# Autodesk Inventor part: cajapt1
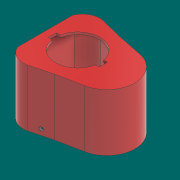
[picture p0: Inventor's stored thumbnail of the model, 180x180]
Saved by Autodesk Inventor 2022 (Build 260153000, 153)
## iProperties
Created: 2021-11
Part Number: cajapt1
Material: Generic
Document SubType Name: Modeling
Designer: santi
Density: 1 g/cm^3
Appearance: Default
Author: santi
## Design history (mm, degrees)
sketch "Sketch1"
  geometry: C1 r 21 at (0, 0); C2 r 20 at (0, 0); 1 further point
  constraints: 2 centre point, 1 coincident
  dimensions: "d0" = 42 diameter of C1; "d1" = 1 radial gap between concentric circles of C1 C2
extrude "Extrusion1" new body sketch "Sketch1" distance "d2" = 15; taper "d3" = 0 deg
sketch "Sketch2" dims "d4" = 48
  geometry: L1 (-24, 0)-(-24, 5.5); L2 (-24, 5.5)-(-24, -5.5); L3 (-24, -5.5)-(-20.267, -5.5); L4 (-24, 5.5)-(-20.267, 5.5); L5 (0, 0)-(0, 10.729); L6 (24, 0)-(24, 5.5); L7 (24, 5.5)-(24, -5.5); L8 (24, -5.5)-(20.267, -5.5); L9 (24, 5.5)-(20.267, 5.5); L10 (23, 5.5)-(23, -4.5); L11 (23, -4.5)-(20.267, -4.5); L12 (24, 4.5)-(20.267, 4.5); L13 (-23, 5.5)-(-23, -4.5); L14 (-23, -4.5)-(-20.267, -4.5); L15 (-24, 4.5)-(-20.267, 4.5); C1 r 21 at (0, 0) reference; C2 r 23 at (0, 0); C3 r 21 at (0, 0); C4 r 23 at (0, 0); A1 r 21 centre (0, 0) between (-20.267, -5.5) and (-20.267, 5.5) reference; A2 r 21 centre (0, 0) between (20.267, -5.5) and (20.267, 5.5); 16 further points
  constraints: 30 end point, 5 symmetric about line, 4 centre point, 4 point on circle, 4 vertical, 2 coincident, 2 parallel, 2 perpendicular, 2 point on line, 1 horizontal alignment, 10 other
  dimensions: "d5" = 1 dimension on C2; "d6" = 5.5 distance of L1.start L1.end; "d7" = 11 distance of L1.end L2.end; "d8" = 1 distance between parallel lines of L7 L10; "d9" = 1 distance between parallel lines of L9 L12; "d10" = 1 distance between parallel lines of L2 L13; "d11" = 1 distance between parallel lines of L4 L15
extrude "Extrusion2" join sketch "Sketch2" distance "d12" = 15; taper "d13" = 0 deg
sketch "Sketch3"
  geometry: L1 (-20.512, 4.5)-(20.512, 4.5); L2 (-20.512, -4.5)-(20.512, -4.5); A1 r 21 centre (0, 0) between (-20.512, 4.5) and (-20.512, -4.5) reference; A2 r 21 centre (0, 0) between (20.512, -4.5) and (20.512, 4.5) reference; A3 r 21 centre (0, 0) between (20.512, -4.5) and (20.512, 4.5) reference; 1 further point
  constraints: 4 end point, 2 horizontal
extrude "Extrusion3" cut sketch "Sketch3" distance "d14" = 15; taper "d15" = 0 deg
workplane "Work Plane1"
sketch "Sketch4"
  geometry: C1 r 15 at (0, 0); 1 further point
  constraints: 1 centre point, 1 coincident
  dimensions: "d17" = 30 diameter of C1
sketch "Sketch5"
  geometry: L1 (-24, -5.5)-(-20.267, -5.5) reference; L2 (-24, 5.5)-(-24, -5.5) reference; L3 (-20.267, 5.5)-(-24, 5.5) reference; L4 (23.361, 5.5)-(20.267, 5.5) reference; L5 (20.267, -5.5)-(23.361, -5.5) reference; A1 r 21 centre (0, 0) between (-20.267, -5.5) and (20.267, -5.5) reference; A2 r 21 centre (0, 0) between (20.267, 5.5) and (-20.267, 5.5) reference; A3 r 24 centre (0, 0) between (23.361, -5.5) and (23.361, 5.5) reference; 1 further point
loft "Loft1" dims "d18" = 0, "d19" = 90 deg, "d20" = 0, "d21" = 90 deg
  node "Edges1"
sketch "Sketch6"
  geometry: C1 r 6.5 at (0, 0); C2 r 5.5 at (0, 0); 1 further point
  constraints: 2 centre point, 1 coincident
  dimensions: "d22" = 13 diameter of C1; "d23" = 1 radial gap between concentric circles of C1 C2
extrude "Extrusion4" join sketch "Sketch6" distance "d24" = 2; taper "d25" = 0 deg
sketch "Sketch7"
  geometry: C1 r 5.5 at (0, 0) reference; 1 further point
extrude "Extrusion5" cut sketch "Sketch7" distance "d26" = 6; taper "d27" = 0 deg
sketch "Sketch8"
  geometry: L1 (-20.19, 4.5)-(-20.19, -5.5); L2 (-20.19, -5.5)-(-20.19, 14.5); C1 r 2.5 at (-20.19, 14.5); C2 r 2.5 at (-20.19, -5.5)
  constraints: 4 end point, 2 centre point, 2 coincident, 1 point on line, 1 vertical
  dimensions: "d28" = 10 distance of L1.start L1.end; "d29" = 20 distance of L1.end L2.end; "d30" = 5 diameter of C1; "d31" = 5 diameter of C2
extrude "Extrusion6" cut sketch "Sketch8" distance "d32" = 10; taper "d33" = 0 deg
workplane "Work Plane2"
sketch "Sketch9"
  geometry: L1 (-20.206, 4.5)-(-22.555, 4.5) reference; L2 (-22.555, -4.5)-(-20.605, -4.5) reference; L3 (-20.605, -4.5)-(-19.487, -4.5) reference; L4 (19.487, -4.5)-(20.19, -4.5) reference; L5 (20.19, -4.5)-(22.555, -4.5) reference; L6 (22.555, 4.5)-(20.206, 4.5) reference; L7 (20.206, 4.5)-(19.487, 4.5) reference; L8 (-19.487, 4.5)-(-20.206, 4.5) reference; L9 (18.675, 3.5)-(21.72, 3.5); L10 (21.72, -3.5)-(20.19, -3.5); L11 (20.19, -3.5)-(18.675, -3.5); L12 (-18.675, -3.5)-(-20.605, -3.5); L13 (-20.605, -3.5)-(-21.72, -3.5); L14 (-21.72, 3.5)-(-18.675, 3.5); C1 r 2.5 at (0, -10) reference; C2 r 2.5 at (0, 10) reference; A1 r 23 centre (0, 0) between (-22.555, 4.5) and (-22.555, -4.5) reference; A2 r 20 centre (0, 0) between (-19.487, -4.5) and (19.487, -4.5) reference; A3 r 23 centre (0, 0) between (22.555, -4.5) and (22.555, 4.5) reference; A4 r 20 centre (0, 0) between (19.487, 4.5) and (-19.487, 4.5) reference; A5 r 19 centre (0, 0) between (18.675, 3.5) and (-18.675, 3.5); A6 r 22 centre (0, 0) between (21.72, -3.5) and (21.72, 3.5); A7 r 19 centre (0, 0) between (-18.675, -3.5) and (18.675, -3.5); A8 r 22 centre (0, 0) between (-21.72, 3.5) and (-21.72, -3.5); 1 further point
  constraints: 12 end point, 8 point on circle, 4 centre point, 9 other
  dimensions: "d35" = 1 radial gap between concentric circles of A4 A5
extrude "Extrusion7" join sketch "Sketch9" distance "d36" = 17; taper "d37" = 0 deg
sketch "Sketch10"
  geometry: L1 (39.295, -21.094)-(-36.743, -21.094); L2 (-36.743, -21.094)-(-30.463, 43.655); L3 (-30.463, 43.655)-(40.715, 44.776); L4 (40.715, 44.776)-(39.295, -21.094); 1 further point
  constraints: 8 end point, 1 horizontal
extrude "Extrusion8" cut sketch "Sketch10" distance "d38" = 50; taper "d39" = 0 deg
sketch "Sketch11"
  geometry: C1 r 2.5 at (0, -10) reference; C2 r 2.5 at (0, 10) reference; 1 further point
extrude "Extrusion9" join sketch "Sketch11" stored distance "d40" = 34; taper "d41" = 0 deg
fillet "Fillet1" dims "d42" = 2.5
sketch "Sketch12"
  geometry: L1 (0, 21.5)-(-10.665, 21.5); L2 (0, -21.5)-(-10.665, -21.5); A1 r 21.5 centre (0, 0) between (0, 21.5) and (0, -21.5); A2 r 24 centre (0, 0) between (-10.665, 21.5) and (-10.665, -21.5); 1 further point
  constraints: 4 end point, 4 point on circle, 2 centre point, 2 coincident, 1 horizontal, 1 parallel, 1 tangent
  dimensions: "d43" = 43 diameter of A1; "d44" = 48 diameter of A2
extrude "Extrusion10" join sketch "Sketch12" distance "d45" = 2; taper "d46" = 0 deg
sketch "Sketch13"
  geometry: L1 (-24, 0)-(-24, -31); L2 (-24, -31)-(-24, 31); L3 (-24, 31)-(7.019, 22.951); L4 (-24, -31)-(6.012, -23.235); A1 r 24 centre (0, 0) between (-10.665, 21.5) and (-10.665, -21.5) reference; A2 r 24 centre (0, 0) between (-10.665, 21.5) and (-10.665, -21.5) reference; A3 r 24 centre (0, 0) between (7.019, 22.951) and (6.012, -23.235); 2 further points
  constraints: 8 end point, 4 point on circle, 2 tangent, 1 centre point, 1 coincident, 1 point on line, 1 vertical
  dimensions: "d47" = 31 distance of L1.start L1.end; "d48" = 62 distance of L1.end L2.end
extrude "Extrusion11" join sketch "Sketch13" distance "d49" = 2; taper "d50" = 0 deg
fillet "Fillet2" dims "d51" = 10
sketch "Sketch14"
  geometry: L1 (0, 1.38)-(-17.471, 1.38); L2 (-17.471, 1.38)-(-17.471, -1.312); L3 (-17.471, -1.312)-(0, -1.312); L4 (0, -1.312)-(0, 1.38); L5 (15.996, -4.2)-(5.478, -4.2); L6 (5.478, -4.2)-(5.478, -6.53); L7 (5.478, -6.53)-(15.996, -6.53); L8 (15.996, -6.53)-(15.996, -4.2); L9 (15.996, 7.583)-(5.478, 7.583); L10 (5.478, 7.583)-(5.478, 3.655); L11 (5.478, 3.655)-(15.996, 3.655); L12 (15.996, 3.655)-(15.996, 7.583); 1 further point
  constraints: 24 end point, 6 parallel, 3 horizontal, 3 perpendicular, 2 point on line
extrude "Extrusion12" cut sketch "Sketch14" distance "d52" = 2; taper "d53" = 0 deg
workplane "Work Plane3"
sketch "Sketch15"
  geometry: L1 (21.72, -3.5)-(18.675, -3.5) reference; L2 (18.675, 3.5)-(21.72, 3.5) reference; L3 (-21.72, 3.5)-(-18.675, 3.5) reference; L4 (-18.675, -3.5)-(-21.72, -3.5) reference; L5 (21.018, 6.5)-(24.14, 6.5); L6 (24.14, -6.5)-(21.018, -6.5); L7 (-21.018, -6.5)-(-24.14, -6.5); L8 (-24.14, 6.5)-(-21.018, 6.5); C1 r 2.5 at (0, -10) reference; C2 r 2.5 at (0, 10) reference; A1 r 19 centre (0, 0) between (-18.675, -3.5) and (18.675, -3.5) reference; A2 r 22 centre (0, 0) between (21.72, -3.5) and (21.72, 3.5) reference; A3 r 19 centre (0, 0) between (18.675, 3.5) and (-18.675, 3.5) reference; A4 r 22 centre (0, 0) between (-21.72, 3.5) and (-21.72, -3.5) reference; A5 r 19 centre (0, 0) between (-18.675, -3.5) and (18.675, -3.5) reference; A6 r 22 centre (0, 0) between (21.018, 6.5) and (-21.018, 6.5); A7 r 25 centre (0, 0) between (24.14, -6.5) and (24.14, 6.5); A8 r 22 centre (0, 0) between (-21.018, -6.5) and (21.018, -6.5); A9 r 25 centre (0, 0) between (-24.14, 6.5) and (-24.14, -6.5); 3 further points
  constraints: 8 end point, 8 point on circle, 4 centre point, 7 other
  dimensions: "d55" = 3 radial gap between concentric circles of A3 A6
extrude "Extrusion13" join sketch "Sketch15" distance "d56" = 2; taper "d57" = 0 deg
sketch "Sketch16"
  geometry: L1 (-25, 0)-(-25, 30); L2 (-25, 0)-(-25, -30); L3 (-11.495, 27.765)-(6.012, 23.235) reference; L4 (7.019, -22.951)-(-11.488, -27.753) reference; L5 (-10.994, 29.701)-(6.513, 25.171); L6 (7.522, -24.886)-(-10.986, -29.689); L7 (6.513, 25.171)-(29.169, 20.582); L8 (7.522, -24.886)-(29.095, -20.597); L9 (-10.994, 29.701)-(6.513, 25.171); L10 (-10.986, -29.689)-(7.522, -24.886); L11 (24.14, 6.5)-(21.018, 6.5) reference; L12 (-21.018, 6.5)-(-24.14, 6.5) reference; L13 (-24.14, -6.5)-(-21.018, -6.5) reference; L14 (21.018, -6.5)-(24.14, -6.5) reference; L15 (21.72, -3.5)-(18.675, -3.5) reference; L16 (-18.675, -3.5)-(-21.72, -3.5) reference; L17 (-21.72, 3.5)-(-18.675, 3.5) reference; L18 (18.675, 3.5)-(21.72, 3.5) reference; A1 r 25 centre (0, 0) between (-24.14, 6.5) and (-24.14, -6.5) reference; A2 r 25 centre (0, 0) between (24.14, -6.5) and (24.14, 6.5) reference; A3 r 25 centre (0, 0) between (24.14, -6.5) and (24.14, 6.5) reference; A4 r 21 centre (25, 0) between (29.095, -20.597) and (29.169, 20.582); A5 r 10 centre (-14, 18.083) between (-11.495, 27.765) and (-24, 18.083) reference; A6 r 12 centre (-14, 18.083) between (-10.994, 29.701) and (-25, 22.879); A7 r 10 centre (-14, -18.074) between (-24, -18.074) and (-11.488, -27.753) reference; A8 r 12 centre (-14, -18.074) between (-25, -22.87) and (-10.986, -29.689); A9 r 22 centre (0, 0) between (21.018, 6.5) and (-21.018, 6.5) reference; A10 r 25 centre (0, 0) between (-24.14, 6.5) and (-24.14, -6.5) reference; A11 r 22 centre (0, 0) between (-21.018, -6.5) and (21.018, -6.5) reference; A12 r 25 centre (0, 0) between (24.14, -6.5) and (24.14, 6.5) reference; A13 r 19 centre (0, 0) between (-18.675, -3.5) and (18.675, -3.5) reference; A14 r 22 centre (0, 0) between (-21.72, 3.5) and (-21.72, -3.5) reference; A15 r 19 centre (0, 0) between (18.675, 3.5) and (-18.675, 3.5) reference; A16 r 22 centre (0, 0) between (21.72, -3.5) and (21.72, 3.5) reference; 7 further points
  constraints: 16 end point, 9 point on circle, 4 tangent, 3 centre point, 2 parallel, 2 point on line, 2 vertical
  dimensions: "d58" = 30 distance of L1.start L1.end; "d59" = 30 distance of L1.start L2.end; "d60" = 42 diameter of A4; "d61" = 2 distance between parallel lines of L3 L5; "d62" = 2 distance between parallel lines of L4 L6; "d63" = 2 radial gap between concentric circles of A5 A6; "d64" = 2 radial gap between concentric circles of A7 A8
extrude "Extrusion14" join sketch "Sketch16" distance "d65" = 2; taper "d66" = 0 deg
sketch "Sketch17"
  geometry: L1 (0, 1.312)-(-17.471, 1.312) reference; L2 (-17.471, 1.312)-(-17.471, -1.38) reference; L3 (-17.471, -1.38)-(0, -1.38) reference; L4 (0, -1.38)-(0, 1.312) reference; L5 (-11.495, 27.765)-(6.012, 23.235) reference; L6 (7.019, -22.951)-(-11.488, -27.753) reference; L7 (-24, -18.074)-(-24, 18.083) reference; L8 (0, 1.312)-(-17.471, 1.312) reference; L9 (0, 1.312)-(-17.471, 1.312) reference; A1 r 10 centre (-14, 18.083) between (-11.495, 27.765) and (-24, 18.083) reference; A2 r 24 centre (0, 0) between (7.019, -22.951) and (6.012, 23.235) reference; A3 r 10 centre (-14, -18.074) between (-24, -18.074) and (-11.488, -27.753) reference; 1 further point
extrude "Extrusion15" cut sketch "Sketch17" distance "d67" = 55; taper "d68" = 0 deg
sketch "Sketch18"
  geometry: L1 (-25, 22.87)-(-25, -22.879) reference; L2 (7.522, 24.886)-(-10.986, 29.689) reference; L3 (29.095, 20.597)-(7.522, 24.886) reference; L4 (6.513, -25.171)-(29.169, -20.582) reference; L5 (-10.994, -29.701)-(6.513, -25.171) reference; L6 (-10.243, -32.605)-(7.187, -28.096); L7 (7.187, -28.096)-(29.765, -23.522); L8 (29.68, 23.539)-(8.192, 27.812); L9 (8.192, 27.812)-(-10.232, 32.593); L10 (-28, 23.459)-(-28, -23.468); A1 r 12 centre (-14, -18.083) between (-25, -22.879) and (-10.994, -29.701) reference; A2 r 12 centre (-14, 18.074) between (-10.986, 29.689) and (-25, 22.87) reference; A3 r 21 centre (25, 0) between (29.169, -20.582) and (29.095, 20.597) reference; A4 r 15 centre (-14, -18.083) between (-28, -23.468) and (-10.243, -32.605); A5 r 24 centre (25, 0) between (29.765, -23.522) and (29.68, 23.539); A6 r 15 centre (-14, 18.074) between (-10.232, 32.593) and (-28, 23.459); 1 further point
  constraints: 10 end point, 6 point on circle, 3 centre point, 7 other
  dimensions: "d69" = 3 distance between parallel lines of L1 L10
extrude "Extrusion16" join sketch "Sketch18" distance "d70" = 2; taper "d71" = 0 deg
sketch "Sketch19"
  geometry: L1 (8.192, 27.812)-(-10.232, 32.593) reference; L2 (29.68, 23.539)-(8.192, 27.812) reference; L3 (7.187, -28.096)-(29.765, -23.522) reference; L4 (-10.243, -32.605)-(7.187, -28.096) reference; L5 (-28, 23.459)-(-28, -23.468) reference; L6 (-10.735, 30.657)-(7.745, 25.862); L7 (7.745, 25.862)-(29.29, 21.578); L8 (29.367, -21.562)-(6.737, -26.146); L9 (6.737, -26.146)-(-10.744, -30.669); L10 (-26, -23.083)-(-26, 23.074); A1 r 15 centre (-14, 18.074) between (-10.232, 32.593) and (-28, 23.459) reference; A2 r 24 centre (25, 0) between (29.765, -23.522) and (29.68, 23.539) reference; A3 r 15 centre (-14, -18.083) between (-28, -23.468) and (-10.243, -32.605) reference; A4 r 13 centre (-14, 18.074) between (-10.735, 30.657) and (-26, 23.074); A5 r 22 centre (25, 0) between (29.367, -21.562) and (29.29, 21.578); A6 r 13 centre (-14, -18.083) between (-26, -23.083) and (-10.744, -30.669); 1 further point
  constraints: 10 end point, 6 point on circle, 3 centre point, 7 other
  dimensions: "d72" = 2 radial gap between concentric circles of A1 A4
extrude "Extrusion17" join sketch "Sketch19" distance "d73" = 47; taper "d74" = 0 deg
sketch "Sketch20"
  geometry: L1 (19.092, 0)-(0, 0) reference; L2 (9.546, 0)-(9.546, 5); C1 r 1.5 at (9.546, 5); 1 further point
  constraints: 2 end point, 1 centre point, 1 coincident, 1 midpoint, 1 vertical
  dimensions: "d75" = 5 distance of L2.start L2.end; "d76" = 3 diameter of C1
extrude "Extrusion18" cut sketch "Sketch20" distance "d77" = 47; taper "d78" = 0 deg
sketch "Sketch21"
  geometry: L1 (-18.057, 0)-(0, 0) reference; L2 (-9.028, 0)-(-9.028, 5); C1 r 1.5 at (-9.028, 5); 1 further point
  constraints: 2 end point, 1 centre point, 1 coincident, 1 midpoint, 1 vertical
  dimensions: "d79" = 5 distance of L2.start L2.end; "d80" = 3 diameter of C1
extrude "Extrusion19" cut sketch "Sketch21" distance "d81" = 47; taper "d82" = 0 deg
body "Solid1"
node "Projected Loop1"
node "Projected Loop2"
node "Projected Loop3"
node "Projected Loop4"
node "Projected Loop5"
node "Projected Loop6"
